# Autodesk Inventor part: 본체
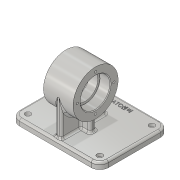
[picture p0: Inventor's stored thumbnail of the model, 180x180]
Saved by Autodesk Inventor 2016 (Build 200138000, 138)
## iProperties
Created: 2019-09
Part Number: 본체
Material: 알루미늄 6061
Document SubType Name: Modeling
Designer: Administrator
Density: 2.7 g/cm^3
Appearance: 알루미늄 - 평지
Mass: 554.62 g
Surface Area: 495.884 cm^2
Volume: 205.415 cm^3
Author: Administrator
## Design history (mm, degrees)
sketch "스케치1"
  geometry: L1 (-21, 0)-(21, 0); L2 (-21, 21)-(-6, 21); L3 (-6, 21)-(-6, 18); L4 (-6, 18)-(6, 18); L5 (6, 18)-(6, 21); L6 (6, 21)-(21, 21); L7 (21, 21)-(21, 32); L8 (21, 32)-(-21, 32); L9 (-21, 32)-(-21, 21); 2 further points
  constraints: 18 end point, 4 perpendicular, 2 horizontal, 2 point on line, 2 vertical alignment, 1 coincident, 1 midpoint, 1 parallel, 1 vertical
  dimensions: "d0" = 42 distance of L1.start L1.end; "d1" = 15 distance of L2.start L2.end; "d2" = 15 distance of L5.end L6.end; "d3" = 36 diameter of L4 L1; "d4" = 42 diameter of L6 L1; "d5" = 64 diameter of L8 L1
revolve "회전1" sketch "스케치1" stored, may be unused: angle "d6" = 90 deg
sketch "스케치2"
  geometry: L1 (63, -59)-(-63, -59); L2 (-63, -59)-(-63, -50); L3 (-63, -50)-(63, -50); L4 (63, -50)-(63, -59); 1 further point
  constraints: 8 end point, 2 parallel, 1 horizontal, 1 perpendicular
  dimensions: "d7" = 63 distance from line of L2 point (0, 0); "d8" = 126 distance of L2.end L3.end; "d10" = 59 distance from line of L1 point (0, 0); "d11" = 9 distance between parallel lines of L1 L3
extrude "돌출1" join sketch "스케치2" distance "d12" = 62; taper "d13" = 0 deg; dims "d14" = 36, "d15" = 0
sketch "스케치3"
  geometry: L1 (-32, 0)-(-32, -50); L2 (62, -50)-(-36, -50) reference; L3 (32, 0)-(32, -50); A1 r 32 centre (0, 0) between (-32, 0) and (32, 0) reference; 1 further point
  constraints: 4 end point, 2 point on circle, 2 point on line, 2 tangent, 1 parallel, 1 vertical
extrude "돌출2" join sketch "스케치3" stored distance "d16" = 8; taper "d17" = 0 deg
sketch "스케치4"
  geometry: L1 (46, -58)-(80, -58); L2 (80, -58)-(80, -66); L3 (80, -66)-(46, -66); L4 (46, -66)-(46, -58); 3 further points
  constraints: 8 end point, 2 midpoint, 2 parallel, 1 horizontal, 1 horizontal alignment, 1 perpendicular, 1 vertical alignment
  dimensions: "d20" = 34 distance between parallel lines of L2 L4; "d21" = 8 distance between parallel lines of L3 L1
extrude "돌출3" join sketch "스케치4" stored distance "d22" = 8; taper "d23" = 0 deg; dims "d7" = 63, "d8" = 126, "d10" = 59, "d11" = 9
sketch "스케치5"
  geometry: L1 (126, -98)-(0, -98) reference; L2 (0, 0)-(0, -98) reference; 2 further points
  dimensions: "d24" = 12 distance from line of point (12, -86) L1; "d25" = 12 distance from line of point (12, -86) L2
hole "구멍1" sketch "스케치5" at (12, -86) diameter "d26" = 4.5; stored, may be unused: countersink angle "d30" = 90 deg, drill point angle "d32" = 118 deg; dims "d27" = 6, "d28" = 8, "d29" = 4.4, "d31" = 8
sketch "스케치6" dims "d39" = 52
  geometry: 3 further points
  constraints: 2 horizontal alignment, 1 coincident, 2 other
hole "구멍2" sketch "스케치6" at (-26, 0) diameter "d40" = 3.242; stored, may be unused: countersink angle "d44" = 90 deg, drill point angle "d46" = 118 deg; dims "d41" = 8, "d42" = 8, "d43" = 4.4, "d45" = 10
chamfer "모따기1" distance "d50" = 1; stored, may be unused: second distance "d51" = 2, angle "d52" = 45 deg
fillet "모깎기1" dims "d53" = 0.3
fillet "모깎기2" dims "d54" = 12
fillet "모깎기3" dims "d55" = 3
fillet "모깎기4" dims "d56" = 3
sketch "스케치7"
  geometry: L1 (102, 3)-(0, 3) reference; L2 (114, -83)-(114, -9) reference; 2 further points
  constraints: 1 other
  dimensions: "d57" = 10 distance from line of L1 point (51, -7); "d58" = 63 distance from line of point (51, -7) L2
feature "엠보싱1" sketch "스케치7" dims "d0" = 42, "d1" = 15, "d2" = 15, "d3" = 36, "d4" = 42, "d5" = 64, "d59" = 0.5, "d60" = 0
node "솔리드1"
pattern_linear "직사각형 패턴1" dims "d35" = 74, "d38" = 102
pattern_circular "원형 패턴1" dims angle "d48" = 360 deg
mirror "대칭1"
